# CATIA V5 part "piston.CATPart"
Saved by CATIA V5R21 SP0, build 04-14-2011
Part number: piston
Material "Gris bleu": density 7860 kg/m3, Young's modulus 2e+11 Pa, Poisson ratio 0.266
Bounding box of the stored display mesh (mm): x -10.5 to 10.5, y -10.498 to 10.498, z 0 to 18.5
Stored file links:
  C:\Users\Olivier\Desktop\redaction CATIA (local)\CATIA\DONNEES\Exercice assemblage 2 (ensemble piston)\piston.CATPart
  C:\Program Files\Dassault Systemes\B21\win_b64\startup\materials\French\Catalog.CATMaterial
  C:\Users\Olivier\Desktop\redaction CATIA (local)\pompe à moteur de ventilation refait\Pompe_a_moteur_de_ventilation.CATProduct
  C:\Users\Olivier\Desktop\redaction CATIA (local)\pompe à moteur de ventilation refait\Ecrou a collerette M5.CATPart
  C:\Program Files\Dassault Systemes\B21\win_b64\startup\materials\brushed_metal1.jpg
  C:\Program Files\Dassault Systemes\B21\win_b64\startup\materials\eroded_metal_1.jpg
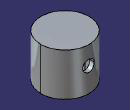
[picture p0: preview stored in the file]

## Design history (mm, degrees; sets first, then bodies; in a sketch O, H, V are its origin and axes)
Body1 (main body), material "Gris bleu"
  Sketch1 on xy-plane, origin (0, 0, 0), H (1, 0, 0), V (0, 1, 0)
    circle A1 centre (0, 0) radius 10.5
  Pad1: profile Sketch1, direction (0, 0, 1), length 18.5
  Sketch2 on start face of Pad1, origin (0, 0, 0), H (1, 0, 0), V (0, -1, 0)
    construction line L1 through (0, 0) direction (0, 1)
    point P1 (0, 2.5)
    construction line L2 (0, 2.5) -> (0, -2.5)
    line L3 (6.25, 2.5) -> (6.25, -2.5)
    arc A1 centre (0, -2.5) radius 6.25 from (6.25, -2.5) to (-6.25, -2.5) cw
    arc A2 centre (0, 2.5) radius 6.25 from (-6.25, 2.5) to (6.25, 2.5) cw
    line L4 (-6.25, -2.5) -> (-6.25, 2.5)
    construction line L5 through (0, 0) direction (1, 0)
    point P2 (0, 0)
    distance L2 L3 = 6.25
    length L2 = 5
    distance P1 L5 = 2.5
    coincidence: P1 L1
    vertical: L2 L1
    tangency: A1 L3, A2 L3, A1 L4, A2 L4
  Pocket1: profile Sketch2, direction (0, 0, 1), length 16.5
  Sketch3 on zx-plane, origin (0, 0, 0), H (-1, 0, 0), V (0, 0, 1)
    circle A1 centre (0, 10.5) radius 2.5
    point P1 (0, 10.5)
    reference projected line E1 (-10.5, 18.5) -> (10.5, 18.5) from edge [face of Pad1 from Sketch1.A1 | end face of Pad1]
    distance P1 E1 = 8
    coincidence: P1 V
  Pocket2: profile Sketch3, direction (0, -1, 0), length 16.5, mirrored extent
